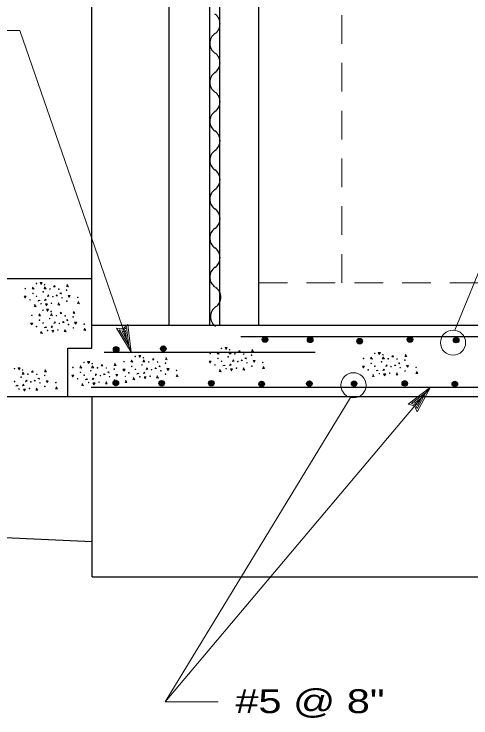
# Model space of a CAD drawing. Extents: x -28.1 to 13.9, y -16.1 to 13.9.
# Drawn here: x -21.699 to -19.308, y -6.899 to -3.215 of the extents above; entities that cross this region are included whole.
import ezdxf

# ---------------------------------------------------------------- set-up
doc = ezdxf.new("R2010")
doc.units = 0
doc.header["$LTSCALE"] = 0.05
doc.linetypes.add('MEDIUM_DASHED', pattern=[4.5, 3, -1.5])
doc.layers.add('1', color=7, linetype='Continuous', lineweight=13)
doc.layers.add('2', color=7, linetype='Continuous', lineweight=13)

msp = doc.modelspace()

# ---------------------------------------------------------------- linework, layer by layer
at = {"layer": '1', "lineweight": 25}
for p, q in [((-21.29204, -4.96431), (-21.29204, -1.55131)), ((-20.88704, -4.84331), (-20.88704, -1.55131)), ((-20.67504, -4.84331), (-20.67504, -1.55131)), ((-20.62204, -4.84331), (-20.62204, -1.55131)), ((-20.41804, -4.84331), (-20.41804, -1.55131)), ((-23.54204, -4.59931), (-21.29004, -4.59931)), ((-21.29204, -4.84331), (-12.68604, -4.84331)), ((-20.51304, -4.90231), (-17.72904, -4.90231)), ((-21.41704, -5.21731), (-21.41704, -4.96431)), ((-21.41504, -4.96431), (-21.29204, -4.96431)), ((-21.22704, -4.98531), (-20.12404, -4.98531)), ((-21.29604, -5.16731), (-17.77004, -5.16731)), ((-23.96004, -5.21731), (-18.27404, -5.21731)), ((-21.29004, -6.16031), (-21.29004, -5.21731)), ((-23.96304, -5.86031), (-21.29004, -5.97531)), ((-21.29004, -6.16031), (-18.02804, -6.16031))]:
    msp.add_line(p, q, dxfattribs=at)
at = {"layer": '1', "linetype": 'MEDIUM_DASHED'}
for p, q in [((-19.98404, -4.62131), (-19.98404, -1.55031)), ((-20.41804, -4.62131), (-12.68204, -4.62131))]:
    msp.add_line(p, q, dxfattribs=at)
at = {"layer": '1'}
for p, q in [((-19.39304, -4.87031), (-18.95004, -3.78931)), ((-21.08604, -4.98531), (-21.16204, -4.85931)), ((-21.12604, -4.87031), (-21.11004, -4.85531)), ((-21.09804, -4.95031), (-21.11004, -4.85531)), ((-21.08604, -4.98531), (-21.10404, -4.83931)), ((-21.09804, -4.95031), (-21.14804, -4.86831)), ((-21.14804, -4.86831), (-21.12604, -4.87031)), ((-21.11004, -4.91631), (-21.13404, -4.87731)), ((-21.13404, -4.87731), (-21.12304, -4.87731)), ((-21.12304, -4.87731), (-21.11604, -4.87131)), ((-21.11004, -4.91631), (-21.11604, -4.87131)), ((-19.52004, -5.16731), (-20.90904, -6.81531)), ((-19.52004, -5.16731), (-19.63704, -5.25731)), ((-19.52004, -5.16731), (-19.58904, -5.29731)), ((-19.93904, -5.22231), (-20.90904, -6.81531)), ((-19.54404, -5.19531), (-19.62004, -5.25431)), ((-19.56704, -5.22331), (-19.60304, -5.25131)), ((-19.54404, -5.19531), (-19.58904, -5.28031)), ((-19.56704, -5.22331), (-19.58804, -5.26431)), ((-19.59904, -5.26031), (-19.62004, -5.25431)), ((-19.59304, -5.25431), (-19.60304, -5.25131)), ((-19.58904, -5.28031), (-19.59904, -5.26031)), ((-19.58804, -5.26431), (-19.59304, -5.25431)), ((-20.90904, -6.81531), (-20.63104, -6.81531))]:
    msp.add_line(p, q, dxfattribs=at)
for points in [[(-21.08604, -4.98531), (-21.66804, -3.30131), (-21.85404, -3.30131)], [(-21.16204, -4.85931), (-21.12804, -4.86231), (-21.10404, -4.83931)], [(-19.58904, -5.29731), (-19.60404, -5.26631), (-19.63704, -5.25731)]]:
    msp.add_lwpolyline(points, dxfattribs=at)
for centre in [(-19.40204, -4.93531), (-19.92304, -5.15831)]:
    msp.add_circle(centre, 0.0658, dxfattribs=at)
at = {"layer": '1', "lineweight": 25}
for centre, radius in [((-20.38557, -4.91859), 0.01445), ((-20.38557, -4.91859), 0.01121), ((-20.38557, -4.91859), 0.00822), ((-20.38557, -4.91859), 0.00415), ((-20.14957, -4.92059), 0.01445), ((-20.14957, -4.92059), 0.01121), ((-20.14957, -4.92059), 0.00822), ((-20.14957, -4.92059), 0.00415), ((-19.89057, -4.92759), 0.01445), ((-19.89057, -4.92759), 0.01121), ((-19.89057, -4.92759), 0.00822), ((-19.89057, -4.92759), 0.00415), ((-19.62757, -4.91859), 0.01445), ((-19.62757, -4.91859), 0.01121), ((-19.62757, -4.91859), 0.00822), ((-19.62757, -4.91859), 0.00415), ((-19.38557, -4.92159), 0.01445), ((-19.38557, -4.92159), 0.01121), ((-19.38557, -4.92159), 0.00822), ((-19.38557, -4.92159), 0.00415), ((-21.16457, -4.97059), 0.01445), ((-21.16457, -4.97059), 0.01121), ((-21.16457, -4.97059), 0.00822), ((-21.16457, -4.97059), 0.00415), ((-20.91757, -4.96659), 0.01445), ((-20.91757, -4.96659), 0.01121), ((-20.91757, -4.96659), 0.00822), ((-20.91757, -4.96659), 0.00415), ((-21.16657, -5.14659), 0.01445), ((-21.16657, -5.14659), 0.01121), ((-21.16657, -5.14659), 0.00822), ((-21.16657, -5.14659), 0.00415), ((-20.92657, -5.14759), 0.01445), ((-20.92657, -5.14759), 0.01121), ((-20.92657, -5.14759), 0.00822), ((-20.92657, -5.14759), 0.00415), ((-20.66657, -5.14759), 0.01445), ((-20.66657, -5.14759), 0.01121), ((-20.66657, -5.14759), 0.00822), ((-20.66657, -5.14759), 0.00415), ((-20.40357, -5.15159), 0.01445), ((-20.40357, -5.15159), 0.01121), ((-20.40357, -5.15159), 0.00822), ((-20.40357, -5.15159), 0.00415), ((-20.15357, -5.14959), 0.01445), ((-20.15357, -5.14959), 0.01121), ((-20.15357, -5.14959), 0.00822), ((-20.15357, -5.14959), 0.00415), ((-19.91957, -5.14959), 0.01445), ((-19.91957, -5.14959), 0.01121), ((-19.91957, -5.14959), 0.00822), ((-19.91957, -5.14959), 0.00415), ((-19.65457, -5.14859), 0.01445), ((-19.65457, -5.14859), 0.01121), ((-19.65457, -5.14859), 0.00822), ((-19.65457, -5.14859), 0.00415), ((-19.39257, -5.15159), 0.01445), ((-19.39257, -5.15159), 0.01121), ((-19.39257, -5.15159), 0.00822), ((-19.39257, -5.15159), 0.00415)]:
    msp.add_circle(centre, radius, dxfattribs=at)
for centre, start, end in [((-20.68254, -3.26631), 304.0772, 55.92281), ((-20.61354, -3.36831), 124.0772, 235.92281), ((-20.68254, -3.47031), 304.0772, 55.92281), ((-20.61354, -3.57231), 124.0772, 235.92281), ((-20.68254, -3.67431), 304.0772, 55.92281), ((-20.61354, -3.77631), 124.0772, 235.92281), ((-20.68254, -3.87831), 304.0772, 55.92281), ((-20.61354, -3.98031), 124.0772, 235.92281), ((-20.68254, -4.08231), 304.0772, 55.92281), ((-20.61354, -4.18431), 124.0772, 235.92281), ((-20.68254, -4.28631), 304.0772, 55.92281), ((-20.61354, -4.38831), 124.0772, 235.92281), ((-20.68254, -4.49031), 304.0772, 55.92281), ((-20.61354, -4.59231), 124.0772, 235.92281), ((-20.67854, -4.69731), 304.0772, 55.92281), ((-20.60954, -4.79931), 124.0772, 235.92281)]:
    msp.add_arc(centre, 0.06157, start, end, dxfattribs=at)
at = {"layer": '2'}
for p, q in [((-21.49204, -4.64131), (-21.48604, -4.63631)), ((-21.45804, -4.78131), (-21.45204, -4.77631)), ((-20.52404, -4.98131), (-20.51804, -4.97631)), ((-19.72204, -5.00731), (-19.71604, -5.00231)), ((-20.97504, -5.02331), (-20.96904, -5.01831)), ((-21.60704, -5.08731), (-21.60104, -5.08231)), ((-21.24304, -5.05431), (-21.23704, -5.04931))]:
    msp.add_line(p, q, dxfattribs=at)
for points in [[(-21.55804, -4.62931), (-21.56304, -4.62031), (-21.55204, -4.62031), (-21.55804, -4.63131)], [(-21.48604, -4.63631), (-21.48404, -4.64331), (-21.49204, -4.64331)], [(-21.41904, -4.63131), (-21.42404, -4.64131), (-21.41404, -4.64231), (-21.42204, -4.63131)], [(-21.59904, -4.64431), (-21.60404, -4.65431), (-21.59404, -4.65531), (-21.60204, -4.64431)], [(-21.53704, -4.64331), (-21.54204, -4.65331), (-21.53104, -4.65431), (-21.53904, -4.64331)], [(-21.45904, -4.67631), (-21.45404, -4.67431), (-21.45104, -4.68031), (-21.45904, -4.67731)], [(-21.64104, -4.70031), (-21.64604, -4.69231), (-21.63504, -4.69231), (-21.64104, -4.70231)], [(-21.57204, -4.71531), (-21.56704, -4.71231), (-21.56304, -4.71531), (-21.57504, -4.71731)], [(-21.47904, -4.68931), (-21.47604, -4.68531), (-21.47104, -4.68931), (-21.47804, -4.69031)], [(-21.41104, -4.69631), (-21.41604, -4.68831), (-21.40504, -4.68831), (-21.41104, -4.69831)], [(-21.58904, -4.73631), (-21.59404, -4.74631), (-21.58404, -4.74731), (-21.59204, -4.73631)], [(-21.53004, -4.74131), (-21.53504, -4.73231), (-21.52404, -4.73231), (-21.53004, -4.74231)], [(-21.46504, -4.72731), (-21.47004, -4.73731), (-21.46004, -4.73831), (-21.46804, -4.72731)], [(-21.36204, -4.72031), (-21.36704, -4.73031), (-21.35704, -4.73131), (-21.36404, -4.72031)], [(-21.56504, -4.78431), (-21.57004, -4.79431), (-21.56004, -4.79531), (-21.56804, -4.78431)], [(-21.52404, -4.76931), (-21.52904, -4.76031), (-21.51804, -4.76031), (-21.52404, -4.77131)], [(-21.50304, -4.78331), (-21.50804, -4.79331), (-21.49704, -4.79431), (-21.50504, -4.78331)], [(-21.45204, -4.77631), (-21.45004, -4.78331), (-21.45804, -4.78331)], [(-21.38504, -4.77131), (-21.39004, -4.78131), (-21.38004, -4.78231), (-21.38804, -4.77131)], [(-21.44504, -4.82931), (-21.44204, -4.82531), (-21.43704, -4.82931), (-21.44404, -4.83031)], [(-21.42504, -4.81631), (-21.42004, -4.81431), (-21.41704, -4.82031), (-21.42504, -4.81731)], [(-21.60704, -4.84031), (-21.61204, -4.83231), (-21.60104, -4.83231), (-21.60704, -4.84231)], [(-21.53804, -4.85531), (-21.53304, -4.85231), (-21.52904, -4.85531), (-21.54104, -4.85731)], [(-21.37704, -4.83631), (-21.38204, -4.82831), (-21.37104, -4.82831), (-21.37704, -4.83831)], [(-21.32804, -4.86031), (-21.33304, -4.87031), (-21.32304, -4.87131), (-21.33004, -4.86031)], [(-21.55504, -4.87631), (-21.56004, -4.88631), (-21.55004, -4.88731), (-21.55804, -4.87631)], [(-21.49604, -4.88131), (-21.50104, -4.87231), (-21.49004, -4.87231), (-21.49604, -4.88231)], [(-21.43104, -4.86731), (-21.43604, -4.87731), (-21.42604, -4.87831), (-21.43404, -4.86731)], [(-20.59004, -4.96931), (-20.59504, -4.96031), (-20.58404, -4.96031), (-20.59004, -4.97131)], [(-20.45104, -4.97131), (-20.45604, -4.98131), (-20.44604, -4.98231), (-20.45404, -4.97131)], [(-21.04104, -5.01131), (-21.04604, -5.00231), (-21.03504, -5.00231), (-21.04104, -5.01331)], [(-20.63104, -4.98431), (-20.63604, -4.99431), (-20.62604, -4.99531), (-20.63404, -4.98431)], [(-20.56904, -4.98331), (-20.57404, -4.99331), (-20.56304, -4.99431), (-20.57104, -4.98331)], [(-20.51804, -4.97631), (-20.51604, -4.98331), (-20.52404, -4.98331)], [(-19.82904, -5.01031), (-19.83404, -5.02031), (-19.82404, -5.02131), (-19.83204, -5.01031)], [(-19.78804, -4.99531), (-19.79304, -4.98631), (-19.78204, -4.98631), (-19.78804, -4.99731)], [(-19.76704, -5.00931), (-19.77204, -5.01931), (-19.76104, -5.02031), (-19.76904, -5.00931)], [(-19.71604, -5.00231), (-19.71404, -5.00931), (-19.72204, -5.00931)], [(-19.64904, -4.99731), (-19.65404, -5.00731), (-19.64404, -5.00831), (-19.65204, -4.99731)], [(-21.30904, -5.04231), (-21.31404, -5.03331), (-21.30304, -5.03331), (-21.30904, -5.04431)], [(-21.17004, -5.04431), (-21.17504, -5.05431), (-21.16504, -5.05531), (-21.17304, -5.04431)], [(-21.08204, -5.02631), (-21.08704, -5.03631), (-21.07704, -5.03731), (-21.08504, -5.02631)], [(-21.02004, -5.02531), (-21.02504, -5.03531), (-21.01404, -5.03631), (-21.02204, -5.02531)], [(-20.96904, -5.01831), (-20.96704, -5.02531), (-20.97504, -5.02531)], [(-20.90204, -5.01331), (-20.90704, -5.02331), (-20.89704, -5.02431), (-20.90504, -5.01331)], [(-20.67304, -5.04031), (-20.67804, -5.03231), (-20.66704, -5.03231), (-20.67304, -5.04231)], [(-20.51104, -5.02931), (-20.50804, -5.02531), (-20.50304, -5.02931), (-20.51004, -5.03031)], [(-20.49104, -5.01631), (-20.48604, -5.01431), (-20.48304, -5.02031), (-20.49104, -5.01731)], [(-20.44304, -5.03631), (-20.44804, -5.02831), (-20.43704, -5.02831), (-20.44304, -5.03831)], [(-19.68904, -5.04231), (-19.68404, -5.04031), (-19.68104, -5.04631), (-19.68904, -5.04331)], [(-21.67304, -5.07531), (-21.67804, -5.06631), (-21.66704, -5.06631), (-21.67304, -5.07731)], [(-21.60104, -5.08231), (-21.59904, -5.08931), (-21.60704, -5.08931)], [(-21.53404, -5.07731), (-21.53904, -5.08731), (-21.52904, -5.08831), (-21.53704, -5.07731)], [(-21.35004, -5.05731), (-21.35504, -5.06731), (-21.34504, -5.06831), (-21.35304, -5.05731)], [(-21.28804, -5.05631), (-21.29304, -5.06631), (-21.28204, -5.06731), (-21.29004, -5.05631)], [(-21.23704, -5.04931), (-21.23504, -5.05631), (-21.24304, -5.05631)], [(-21.12404, -5.08231), (-21.12904, -5.07431), (-21.11804, -5.07431), (-21.12404, -5.08431)], [(-20.96204, -5.07131), (-20.95904, -5.06731), (-20.95404, -5.07131), (-20.96104, -5.07231)], [(-20.94204, -5.05831), (-20.93704, -5.05631), (-20.93404, -5.06231), (-20.94204, -5.05931)], [(-20.89404, -5.07831), (-20.89904, -5.07031), (-20.88804, -5.07031), (-20.89404, -5.08031)], [(-20.62104, -5.07631), (-20.62604, -5.08631), (-20.61604, -5.08731), (-20.62404, -5.07631)], [(-20.60404, -5.05531), (-20.59904, -5.05231), (-20.59504, -5.05531), (-20.60704, -5.05731)], [(-20.56204, -5.08131), (-20.56704, -5.07231), (-20.55604, -5.07231), (-20.56204, -5.08231)], [(-20.49704, -5.06731), (-20.50204, -5.07731), (-20.49204, -5.07831), (-20.50004, -5.06731)], [(-20.39404, -5.06031), (-20.39904, -5.07031), (-20.38904, -5.07131), (-20.39604, -5.06031)], [(-19.87104, -5.06631), (-19.87604, -5.05831), (-19.86504, -5.05831), (-19.87104, -5.06831)], [(-19.80204, -5.08131), (-19.79704, -5.07831), (-19.79304, -5.08131), (-19.80504, -5.08331)], [(-19.70904, -5.05531), (-19.70604, -5.05131), (-19.70104, -5.05531), (-19.70804, -5.05631)], [(-19.64104, -5.06231), (-19.64604, -5.05431), (-19.63504, -5.05431), (-19.64104, -5.06431)], [(-21.65204, -5.08931), (-21.65704, -5.09931), (-21.64604, -5.10031), (-21.65404, -5.08931)], [(-21.57404, -5.12231), (-21.56904, -5.12031), (-21.56604, -5.12631), (-21.57404, -5.12331)], [(-21.39204, -5.11331), (-21.39704, -5.10531), (-21.38604, -5.10531), (-21.39204, -5.11531)], [(-21.23004, -5.10231), (-21.22704, -5.09831), (-21.22204, -5.10231), (-21.22904, -5.10331)], [(-21.21004, -5.08931), (-21.20504, -5.08731), (-21.20204, -5.09331), (-21.21004, -5.09031)], [(-21.16204, -5.10931), (-21.16704, -5.10131), (-21.15604, -5.10131), (-21.16204, -5.11131)], [(-21.07204, -5.11831), (-21.07704, -5.12831), (-21.06704, -5.12931), (-21.07504, -5.11831)], [(-21.05504, -5.09731), (-21.05004, -5.09431), (-21.04604, -5.09731), (-21.05804, -5.09931)], [(-21.01304, -5.12331), (-21.01804, -5.11431), (-21.00704, -5.11431), (-21.01304, -5.12431)], [(-20.94804, -5.10931), (-20.95304, -5.11931), (-20.94304, -5.12031), (-20.95104, -5.10931)], [(-20.84504, -5.10231), (-20.85004, -5.11231), (-20.84004, -5.11331), (-20.84704, -5.10231)], [(-19.81904, -5.10231), (-19.82404, -5.11231), (-19.81404, -5.11331), (-19.82204, -5.10231)], [(-19.76004, -5.10731), (-19.76504, -5.09831), (-19.75404, -5.09831), (-19.76004, -5.10831)], [(-19.69504, -5.09331), (-19.70004, -5.10331), (-19.69004, -5.10431), (-19.69804, -5.09331)], [(-19.59204, -5.08631), (-19.59704, -5.09631), (-19.58704, -5.09731), (-19.59404, -5.08631)], [(-21.59404, -5.13531), (-21.59104, -5.13131), (-21.58604, -5.13531), (-21.59304, -5.13631)], [(-21.52604, -5.14231), (-21.53104, -5.13431), (-21.52004, -5.13431), (-21.52604, -5.14431)], [(-21.34004, -5.14931), (-21.34504, -5.15931), (-21.33504, -5.16031), (-21.34304, -5.14931)], [(-21.32304, -5.12831), (-21.31804, -5.12531), (-21.31404, -5.12831), (-21.32604, -5.13031)], [(-21.28104, -5.15431), (-21.28604, -5.14531), (-21.27504, -5.14531), (-21.28104, -5.15531)], [(-21.21604, -5.14031), (-21.22104, -5.15031), (-21.21104, -5.15131), (-21.21904, -5.14031)], [(-21.11304, -5.13331), (-21.11804, -5.14331), (-21.10804, -5.14431), (-21.11504, -5.13331)], [(-21.68704, -5.16131), (-21.68204, -5.15831), (-21.67804, -5.16131), (-21.69004, -5.16331)], [(-21.64504, -5.18731), (-21.65004, -5.17831), (-21.63904, -5.17831), (-21.64504, -5.18831)], [(-21.58004, -5.17331), (-21.58504, -5.18331), (-21.57504, -5.18431), (-21.58304, -5.17331)], [(-21.47704, -5.16631), (-21.48204, -5.17631), (-21.47204, -5.17731), (-21.47904, -5.16631)]]:
    msp.add_lwpolyline(points, dxfattribs=at)
for points in [[(-21.53904, -4.71531), (-21.53404, -4.70731), (-21.53104, -4.71331)], [(-21.52404, -4.69431), (-21.51904, -4.68531), (-21.51604, -4.69131)], [(-21.49004, -4.83431), (-21.48504, -4.82531), (-21.48204, -4.83131)], [(-21.50504, -4.85531), (-21.50004, -4.84731), (-21.49704, -4.85331)], [(-20.55604, -5.03431), (-20.55104, -5.02531), (-20.54804, -5.03131)], [(-21.00704, -5.07631), (-21.00204, -5.06731), (-20.99904, -5.07331)], [(-20.57104, -5.05531), (-20.56604, -5.04731), (-20.56304, -5.05331)], [(-19.76904, -5.08131), (-19.76404, -5.07331), (-19.76104, -5.07931)], [(-19.75404, -5.06031), (-19.74904, -5.05131), (-19.74604, -5.05731)], [(-21.29004, -5.12831), (-21.28504, -5.12031), (-21.28204, -5.12631)], [(-21.27504, -5.10731), (-21.27004, -5.09831), (-21.26704, -5.10431)], [(-21.02204, -5.09731), (-21.01704, -5.08931), (-21.01404, -5.09531)], [(-21.65404, -5.16131), (-21.64904, -5.15331), (-21.64604, -5.15931)], [(-21.63904, -5.14031), (-21.63404, -5.13131), (-21.63104, -5.13731)]]:
    msp.add_lwpolyline(points, close=True, dxfattribs=at)
for centre in [(-21.58179, -4.62544), (-21.53904, -4.63219), (-21.64004, -4.65219), (-21.60029, -4.67744), (-21.54654, -4.66919), (-21.51129, -4.65394), (-21.46504, -4.65494), (-21.42379, -4.66069), (-21.61554, -4.71119), (-21.58104, -4.69269), (-21.49604, -4.69444), (-21.44804, -4.70019), (-21.36554, -4.69844), (-21.55754, -4.73144), (-21.50354, -4.72894), (-21.42279, -4.71794), (-21.54779, -4.76544), (-21.50504, -4.77219), (-21.60604, -4.79219), (-21.56629, -4.81744), (-21.51254, -4.80919), (-21.47729, -4.79394), (-21.43104, -4.79494), (-21.38979, -4.80069), (-21.58154, -4.85119), (-21.54704, -4.83269), (-21.46204, -4.83444), (-21.41404, -4.84019), (-21.38879, -4.85794), (-21.33154, -4.83844), (-21.52354, -4.87144), (-21.46954, -4.86894), (-20.61379, -4.96544), (-20.57104, -4.97219), (-21.06479, -5.00744), (-20.67204, -4.99219), (-20.57854, -5.00919), (-20.54329, -4.99394), (-20.49704, -4.99494), (-20.45579, -5.00069), (-19.81179, -4.99144), (-19.76904, -4.99819), (-21.33279, -5.03844), (-21.29004, -5.04519), (-21.12304, -5.03419), (-21.02204, -5.01419), (-20.99429, -5.03594), (-20.94804, -5.03694), (-20.90679, -5.04269), (-20.63229, -5.01744), (-20.61304, -5.03269), (-20.52804, -5.03444), (-20.48004, -5.04019), (-20.39754, -5.03844), (-19.87004, -5.01819), (-19.83029, -5.04344), (-19.77654, -5.03519), (-19.74129, -5.01994), (-19.69504, -5.02094), (-19.65379, -5.02669), (-21.69679, -5.07144), (-21.65404, -5.07819), (-21.39104, -5.06519), (-21.29754, -5.08219), (-21.26229, -5.06694), (-21.21604, -5.06794), (-21.17479, -5.07369), (-21.08329, -5.05944), (-21.06404, -5.07469), (-21.02954, -5.05119), (-20.97904, -5.07644), (-20.93104, -5.08219), (-20.84854, -5.08044), (-20.64754, -5.05119), (-20.58954, -5.07144), (-20.53554, -5.06894), (-20.45479, -5.05794), (-19.84554, -5.07719), (-19.81104, -5.05869), (-19.72604, -5.06044), (-19.67804, -5.06619), (-19.65279, -5.08394), (-19.59554, -5.06444), (-21.66154, -5.11519), (-21.62629, -5.09994), (-21.58004, -5.10094), (-21.53879, -5.10669), (-21.35129, -5.09044), (-21.33204, -5.10569), (-21.24704, -5.10744), (-21.19904, -5.11319), (-21.11654, -5.11144), (-21.09854, -5.09319), (-21.04054, -5.11344), (-20.98654, -5.11094), (-20.90579, -5.09994), (-19.78754, -5.09744), (-19.73354, -5.09494), (-21.69604, -5.13869), (-21.61104, -5.14044), (-21.56304, -5.14619), (-21.48054, -5.14444), (-21.36654, -5.12419), (-21.30854, -5.14444), (-21.25454, -5.14194), (-21.17379, -5.13094), (-21.67254, -5.17744), (-21.61854, -5.17494), (-21.53779, -5.16394)]:
    msp.add_circle(centre, 0.00162, dxfattribs=at)

# ---------------------------------------------------------------- texts
at = {"layer": '1', "width": 1.3}
msp.add_text('#5 @ 8"', height=0.125, dxfattribs=at).set_placement((-20.54104, -6.87431))

doc.saveas('drawing.dxf')
